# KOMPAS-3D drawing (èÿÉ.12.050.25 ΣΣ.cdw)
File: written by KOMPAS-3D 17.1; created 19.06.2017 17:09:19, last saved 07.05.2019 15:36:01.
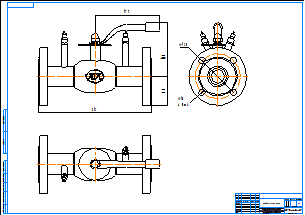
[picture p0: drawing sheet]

Sheet 1: A1, landscape

Title block, sheet 1: name: КШР.12.050.25 фф; material: Внимание! Данный продукт является объектом авторского права ООО «Торговый Дом АДЛ». / Запрещается изменение, копирование, распространение / (в том числе путем копирования на другие сайты и ресурсы в Интернете) / или любое иное использование информации и объектов без предварительного / согласия правообладателя (ООО «Торговый Дом АДЛ»).; scale: 1:1; sheets: 1; organisation: ООО "Торговый дом АДЛ"; sheet format: A1; stored path: C:\Users\tra\Desktop\2д чертежи\Шаровые краны БИВАЛ\КШР_Бивал_серия_12\KOMPAS 2D\КШР.12.050.25 фф.cdw

Views: Спереди 1, Проекционный вид 2, Проекционный вид 3
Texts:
  Klimkovich
  ADL
Dimensions and other numbers on the sheet: 312; 179; 148; 80; 125; 18; 4 Отв.; 1:1; 1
